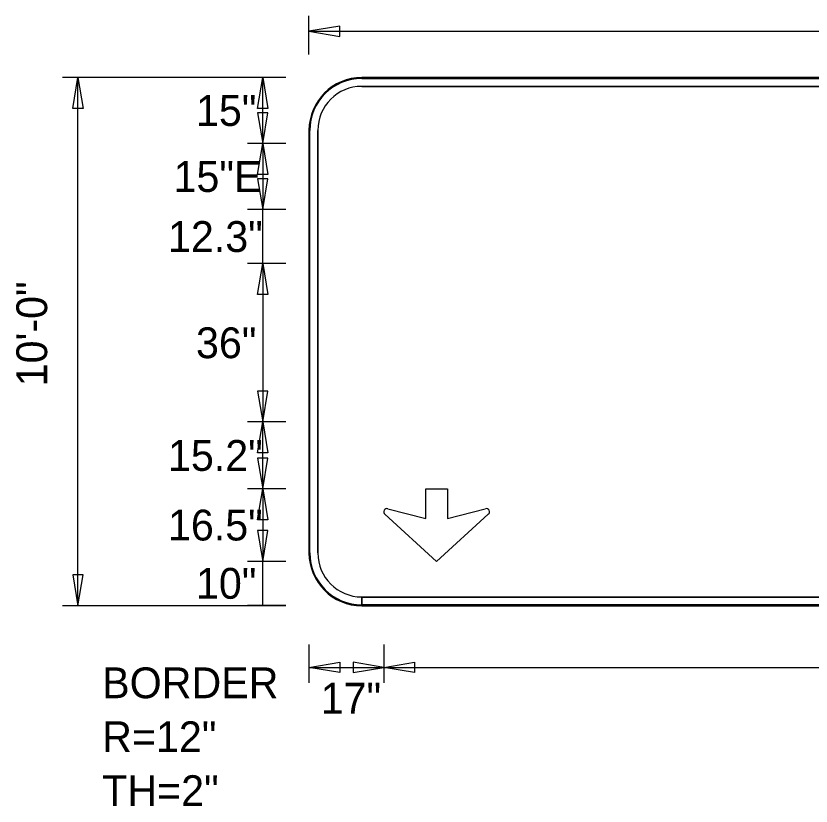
# Model space of a CAD drawing. Extents: x 2149934 to 2150188, y 145113 to 145238.
# Drawn here: x 2149934.05 to 2149949.1, y 145134.16 to 145149.12 of the extents above; entities that cross this region are included whole.
import ezdxf

# ---------------------------------------------------------------- set-up
doc = ezdxf.new("R2010")
doc.units = 0
for name, color, linetype in [('GSBWFILL', 7, 'Continuous'), ('GSCOLORFILL', 7, 'Continuous'), ('GSDIMS', 7, 'Continuous'), ('GSOUTLINE', 7, 'Continuous')]:
    doc.layers.add(name, color=color, linetype=linetype)

msp = doc.modelspace()

# ---------------------------------------------------------------- linework, layer by layer
at = {"layer": 'GSBWFILL'}
for p, q in [((2149965.596, 145147.954), (2149940.596, 145147.954)), ((2149940.596, 145147.787), (2149965.596, 145147.787)), ((2149939.596, 145146.954), (2149939.596, 145138.954)), ((2149939.763, 145138.954), (2149939.763, 145146.954)), ((2149940.596, 145137.954), (2149940.596, 145138.12)), ((2149965.596, 145138.12), (2149940.598, 145138.12)), ((2149940.598, 145138.12), (2149940.598, 145137.954)), ((2149940.598, 145137.954), (2149965.596, 145137.954))]:
    msp.add_line(p, q, dxfattribs=at)
for points in [[(2149941.09, 145139.792), (2149941.81, 145139.607), (2149941.81, 145140.168), (2149942.216, 145140.168), (2149942.216, 145139.607), (2149942.935, 145139.792)], [(2149942.992, 145139.687), (2149942.013, 145138.795), (2149941.033, 145139.687)]]:
    msp.add_lwpolyline(points, dxfattribs=at)
for centre, radius, start, end in [((2149940.596, 145146.954), 1, 90, 180), ((2149940.596, 145146.954), 0.833, 90, 180), ((2149941.075, 145139.732), 0.0615, 75.5925, 227.6952), ((2149942.951, 145139.732), 0.0615, 312.3048, 104.4075), ((2149940.596, 145138.954), 1, 180, 270), ((2149940.596, 145138.954), 0.833, 180, 270)]:
    msp.add_arc(centre, radius, start, end, dxfattribs=at)
at = {"layer": 'GSCOLORFILL'}
for p, q in [((2149965.596, 145147.954), (2149940.596, 145147.954)), ((2149965.596, 145147.954), (2149940.596, 145147.954)), ((2149965.596, 145147.954), (2149940.596, 145147.954)), ((2149940.596, 145147.937), (2149965.596, 145147.937)), ((2149940.596, 145147.787), (2149965.596, 145147.787)), ((2149939.596, 145146.954), (2149939.596, 145138.954)), ((2149939.596, 145146.954), (2149939.596, 145138.954)), ((2149939.596, 145146.954), (2149939.596, 145138.954)), ((2149939.613, 145138.954), (2149939.613, 145146.954)), ((2149939.763, 145138.954), (2149939.763, 145146.954)), ((2149940.596, 145137.954), (2149940.596, 145138.12)), ((2149965.596, 145138.12), (2149940.598, 145138.12)), ((2149940.598, 145138.12), (2149940.598, 145137.954)), ((2149940.596, 145137.954), (2149940.596, 145137.97)), ((2149965.596, 145137.97), (2149940.596, 145137.97)), ((2149940.596, 145137.97), (2149940.596, 145137.954)), ((2149940.596, 145137.954), (2149965.596, 145137.954)), ((2149940.596, 145137.954), (2149965.596, 145137.954)), ((2149940.598, 145137.954), (2149965.596, 145137.954))]:
    msp.add_line(p, q, dxfattribs=at)
for points in [[(2149941.09, 145139.792), (2149941.81, 145139.607), (2149941.81, 145140.168), (2149942.216, 145140.168), (2149942.216, 145139.607), (2149942.935, 145139.792)], [(2149942.992, 145139.687), (2149942.013, 145138.795), (2149941.033, 145139.687)]]:
    msp.add_lwpolyline(points, dxfattribs=at)
for centre, radius, start, end in [((2149940.596, 145146.954), 1, 90, 180), ((2149940.596, 145146.954), 1, 90, 180), ((2149940.596, 145146.954), 1, 90, 180), ((2149940.596, 145146.954), 0.983, 90, 180), ((2149940.596, 145146.954), 0.833, 90, 180), ((2149941.075, 145139.732), 0.0615, 75.5925, 227.6952), ((2149942.951, 145139.732), 0.0615, 312.3048, 104.4075), ((2149940.596, 145138.954), 1, 180, 270), ((2149940.596, 145138.954), 1, 180, 270), ((2149940.596, 145138.954), 1, 180, 270), ((2149940.596, 145138.954), 0.983, 180, 270), ((2149940.596, 145138.954), 0.833, 180, 270)]:
    msp.add_arc(centre, radius, start, end, dxfattribs=at)
at = {"layer": 'GSDIMS'}
for p, q in [((2149939.596, 145148.391), (2149939.596, 145149.12)), ((2149939.596, 145148.829), (2149966.596, 145148.829)), ((2149939.596, 145148.391), (2149939.596, 145148.391)), ((2149935.659, 145147.954), (2149934.93, 145147.954)), ((2149935.221, 145137.954), (2149935.221, 145147.954)), ((2149939.159, 145147.954), (2149935.659, 145147.954)), ((2149939.159, 145147.954), (2149938.43, 145147.954)), ((2149938.721, 145146.705), (2149938.721, 145147.954)), ((2149939.159, 145146.705), (2149938.43, 145146.705)), ((2149939.159, 145146.705), (2149938.43, 145146.705)), ((2149938.721, 145146.705), (2149938.721, 145145.455)), ((2149939.159, 145145.455), (2149938.43, 145145.455)), ((2149939.159, 145145.455), (2149938.43, 145145.455)), ((2149938.721, 145144.433), (2149938.721, 145145.455)), ((2149939.159, 145144.433), (2149938.43, 145144.433)), ((2149939.159, 145144.433), (2149938.43, 145144.433)), ((2149938.721, 145144.433), (2149938.721, 145141.433)), ((2149939.159, 145141.433), (2149938.43, 145141.433)), ((2149939.159, 145141.433), (2149938.43, 145141.433)), ((2149938.721, 145140.168), (2149938.721, 145141.433)), ((2149939.159, 145140.168), (2149938.43, 145140.168)), ((2149939.159, 145140.168), (2149938.43, 145140.168)), ((2149938.721, 145140.168), (2149938.721, 145138.795)), ((2149939.159, 145138.795), (2149938.43, 145138.795)), ((2149939.159, 145138.795), (2149938.43, 145138.795)), ((2149938.721, 145137.962), (2149938.721, 145138.795)), ((2149935.659, 145137.954), (2149934.93, 145137.954)), ((2149939.159, 145137.954), (2149935.659, 145137.954)), ((2149939.159, 145137.962), (2149938.43, 145137.962)), ((2149939.596, 145137.224), (2149939.596, 145136.495)), ((2149939.596, 145137.224), (2149939.596, 145136.495)), ((2149941.013, 145137.224), (2149941.013, 145136.495)), ((2149941.013, 145137.224), (2149941.013, 145136.495)), ((2149939.596, 145136.787), (2149941.013, 145136.787)), ((2149941.013, 145136.787), (2149965.18, 145136.787))]:
    msp.add_line(p, q, dxfattribs=at)
for points in [[(2149939.596, 145148.829), (2149940.18, 145148.732), (2149940.18, 145148.926)], [(2149935.221, 145147.954), (2149935.319, 145147.37), (2149935.124, 145147.37)], [(2149938.721, 145147.954), (2149938.819, 145147.37), (2149938.624, 145147.37)], [(2149938.721, 145146.705), (2149938.819, 145147.288), (2149938.624, 145147.288)], [(2149938.721, 145146.705), (2149938.819, 145146.121), (2149938.624, 145146.121)], [(2149938.721, 145145.455), (2149938.819, 145146.038), (2149938.624, 145146.038)], [(2149938.721, 145144.433), (2149938.819, 145143.849), (2149938.624, 145143.849)], [(2149938.721, 145141.433), (2149938.819, 145142.016), (2149938.624, 145142.016)], [(2149938.721, 145141.433), (2149938.819, 145140.849), (2149938.624, 145140.849)], [(2149938.721, 145140.168), (2149938.819, 145140.751), (2149938.624, 145140.751)], [(2149938.721, 145140.168), (2149938.819, 145139.584), (2149938.624, 145139.584)], [(2149938.721, 145138.795), (2149938.819, 145139.379), (2149938.624, 145139.379)], [(2149935.221, 145137.954), (2149935.319, 145138.537), (2149935.124, 145138.537)], [(2149939.596, 145136.787), (2149940.18, 145136.884), (2149940.18, 145136.69)], [(2149941.013, 145136.787), (2149940.43, 145136.884), (2149940.43, 145136.69)], [(2149941.013, 145136.787), (2149941.596, 145136.884), (2149941.596, 145136.69)]]:
    msp.add_lwpolyline(points, close=True, dxfattribs=at)
at = {"layer": 'GSOUTLINE'}
for p, q in [((2149965.596, 145147.954), (2149940.596, 145147.954)), ((2149965.596, 145147.787), (2149940.596, 145147.787)), ((2149939.596, 145146.954), (2149939.596, 145138.954)), ((2149939.763, 145146.954), (2149939.763, 145138.954)), ((2149940.596, 145138.12), (2149965.596, 145138.12)), ((2149940.596, 145137.954), (2149965.596, 145137.954))]:
    msp.add_line(p, q, dxfattribs=at)
for points in [[(2149941.09, 145139.792), (2149941.81, 145139.607), (2149941.81, 145140.168), (2149942.216, 145140.168), (2149942.216, 145139.607), (2149942.935, 145139.792)], [(2149942.992, 145139.687), (2149942.013, 145138.795), (2149941.033, 145139.687)]]:
    msp.add_lwpolyline(points, dxfattribs=at)
for centre, radius, start, end in [((2149940.596, 145146.954), 1, 90, 180), ((2149940.596, 145146.954), 0.833, 90, 180), ((2149941.075, 145139.732), 0.0615, 75.5925, 227.6952), ((2149942.951, 145139.732), 0.0615, 312.3048, 104.4075), ((2149940.596, 145138.954), 1, 180, 270), ((2149940.596, 145138.954), 0.833, 180, 270)]:
    msp.add_arc(centre, radius, start, end, dxfattribs=at)

# ---------------------------------------------------------------- texts
at = {"layer": 'GSDIMS'}
for s, p in [('15"', (2149937.456, 145147.038)), ('15"E', (2149937.031, 145145.788)), ('12.3"', (2149936.926, 145144.652)), ('36"', (2149937.456, 145142.641)), ('15.2"', (2149936.926, 145140.508)), ('16.5"', (2149936.926, 145139.19)), ('10"', (2149937.456, 145138.087)), ('BORDER', (2149935.68, 145136.204)), ('17"', (2149939.818, 145135.912)), ('R=12"', (2149935.68, 145135.183)), ('TH=2"', (2149935.68, 145134.162))]:
    msp.add_text(s, height=0.5833, dxfattribs=at).set_placement(p)
msp.add_text('10\'-0"', height=0.5833, rotation=90, dxfattribs=at).set_placement((2149934.638, 145142.108))

doc.saveas('drawing.dxf')
